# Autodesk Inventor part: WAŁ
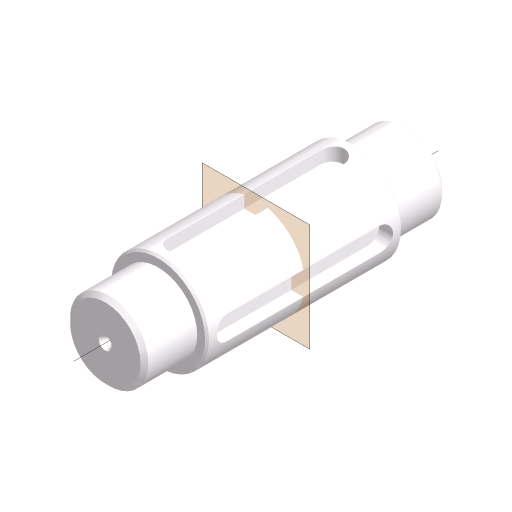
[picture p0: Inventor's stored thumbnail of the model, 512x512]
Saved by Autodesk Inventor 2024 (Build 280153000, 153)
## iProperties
Company: ATC
Shininess: 20.0
Length Units: 11269
Angle Units: 11279
Time Units: 11290
Mass Units: 11283
Length Display Precision: 3
Angle Display Precision: 2
Compacted: True
Created: 2023-03
Part Number: WAŁ
Document SubType Name: Modeling
Designer: Andrzej Jaskulski
Material: Kurs-AJ
Density: 1 g/cm^3
Appearance: Kurs-AJ
Checked By: A.J.
Engr Approved By: Andrzej Jaskulski
Mfg Approved By: Andrzej Jaskulski
Authority: A.J.
Density: 0.0
Volumn: 0.0
Area: 0.0
PropertySet Name: Model Information
Control State: 0
Master: False
Checked Out: False
OBJETOSC: 0,119 l
Title: A.J.: Kurs R2024-MEP
Author: Andrzej Jaskulski
Revision Number: 1/24
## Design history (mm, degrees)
node "Extrusion1" dims "d1" = 50, "d2" = 0
  sketch "Sketch1"
    geometry: C1 r 12.5 at (0, 0)
    constraints: 1 centre point
    dimensions: "d3" = 25 diameter of C1
node "Oś"
node "Pł. Symetrii"
node "Pł. Styczna do Czopa"
node "Extrusion2" dims "d5" = 13.5, "d6" = 0
  sketch "Sketch2"
    geometry: C1 r 12.5 at (0, 0) reference; C2 r 10 at (0, 0)
    constraints: 1 centre point, 1 coincident
    dimensions: "d4" = 20 diameter of C2
node "Hole1" dims "d9" = 1.6, "d10" = 3.35, "d11" = 2, "d12" = 60 deg, "d13" = 4.3, "d14" = 120 deg, "d30" = 6
  sketch "Sketch3"
    geometry: C1 r 10 at (0, 0) reference; 1 further point
    constraints: 1 coincident
node "Chamfer1" dims "d15" = 1, "d16" = 1, "d31" = 45 deg
node "Mirror1"
node "Chamfer2" dims "d17" = 0.5, "d18" = 0.5, "d32" = 45 deg
sketch "Sketch4"
  geometry: L1 (0, -10)-(0, 60) reference; L2 (-12, 50)-(12, 50) reference; L3 (12, 0)-(-12, 0) reference; L4 (-3, 44.5)-(-3, 5.5); L5 (3, 44.5)-(3, 5.5); L6 (-17.5, 25)-(17.5, 25) reference; A1 r 3 centre (0, 44.5) between (3, 44.5) and (-3, 44.5); A2 r 3 centre (0, 5.5) between (-3, 5.5) and (3, 5.5); 2 further points
  constraints: 7 point on circle, 5 point on line, 4 end point, 4 tangent, 2 centre point, 2 parallel
  dimensions: "d20" = 6 distance between parallel lines of L5 L4; "d22" = 22.5 distance from line of point (0, 47.5) L6; "d23" = 22.5 distance from line of point (0, 2.5) L6 (= d22); "d24" = 45 distance of point (0, 2.5) point (0, 47.5) (derived)
extrude "Extrusion3" cut sketch "Sketch4" distance "d25" = 3.5; taper "d26" = 0 deg
pattern_circular "Circular Pattern1" dims angle "d29" = 360 deg
node "Bryła1"
node "Korpusy bryłowe"
node "Korpusy powierzchniowe"
other parameters: "d8" = -25 (= -0.5 x d1), "Lgab" = 77 (= d1 + 2 x d5) [user parameter; used in 1 equation term], "Spreta" = 154.05625 (computed from d3) [user parameter; used in 1 equation term], "OBJETOSC" = 1186.23313 (computed from Lgab, Spreta) [user parameter]
